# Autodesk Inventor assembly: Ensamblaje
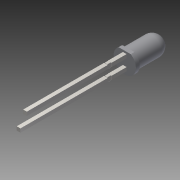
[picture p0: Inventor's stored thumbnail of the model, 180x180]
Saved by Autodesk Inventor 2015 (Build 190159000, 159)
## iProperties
Created: 2016-05
Part Number: Ensamblaje
Document SubType Name: Assembly
Designer: Isra
Author: Isra
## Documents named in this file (3)
- C:\Users\Isra\Documents\Inventor\LED 5mm CAD\Ensamblaje.iam
- C:\Users\Isra\Documents\Inventor\LED 5mm CAD\Led5mm.ipt
- C:\Users\Isra\Documents\Inventor\LED 5mm CAD\Pins.ipt
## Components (2 placed, 2 different names)
1. Led5mm:1
2. Pins:1
